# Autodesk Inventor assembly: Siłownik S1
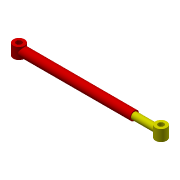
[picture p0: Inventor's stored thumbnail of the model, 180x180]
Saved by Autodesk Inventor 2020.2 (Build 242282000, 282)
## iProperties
Manager: www.cadconsulting.pl
Company: Fabian Stasiak CAD Consulting
Created: 2006-08
Part Number: Siłownik S1
Document SubType Name: Assembly
Designer: F.Stasiak
Author: F.Stasiak
Subject: Zbiór ćwiczeń. Autodesk Inventor 2020. Kurs podstawowy
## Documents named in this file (3)
- C:\2020_Kurs_podstawowy\R6 Zespoły\Lustro\Siłownik S1.iam
- C:\2020_Kurs_podstawowy\R6 Zespoły\Lustro\Cyl1.ipt
- C:\2020_Kurs_podstawowy\R6 Zespoły\Lustro\T1.ipt
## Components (2 placed, 2 different names)
1. Cyl1:1 — Zestawiający:1
2. T1:1 — Zestawiający:1
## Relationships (1: Mate 1)
- Zestawiający:1 [Mate]: Cyl1:1 ↔ T1:1
